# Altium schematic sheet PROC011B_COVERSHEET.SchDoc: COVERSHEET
size 431 x 279 mm; Date: Not shown in title block; ApprovedBy: Not shown in title block; CheckedBy: Not shown in title block; Author: Not shown in title block; CompanyName: Not shown in title block; Engineer: Not shown in title block; Organization: Not shown in title block; Address1: Not shown in title block; Address2: Not shown in title block; Address3: Not shown in title block; Address4: Not shown in title block; DocumentNumber: 1; Revision: Use project parameter SCH_Rev; SheetNumber: 1; SheetTotal: 17; PageSetup: Record=PageOptions¦CenterHorizontal=True¦CenterVertical=True¦PrintScale=0.64¦XCorrection=1.00¦YCorrection=1.00¦PrintKind=0¦BorderSize=5000000¦LeftOffset=0¦BottomOffset=0¦Orientation=2¦PaperLength=1000¦PaperWidth=1000¦Scale=100¦PaperSource=15¦PrintQuality=600¦MediaType=1¦DitherType=10¦PrintScaleMode=1¦PaperKind=Letter
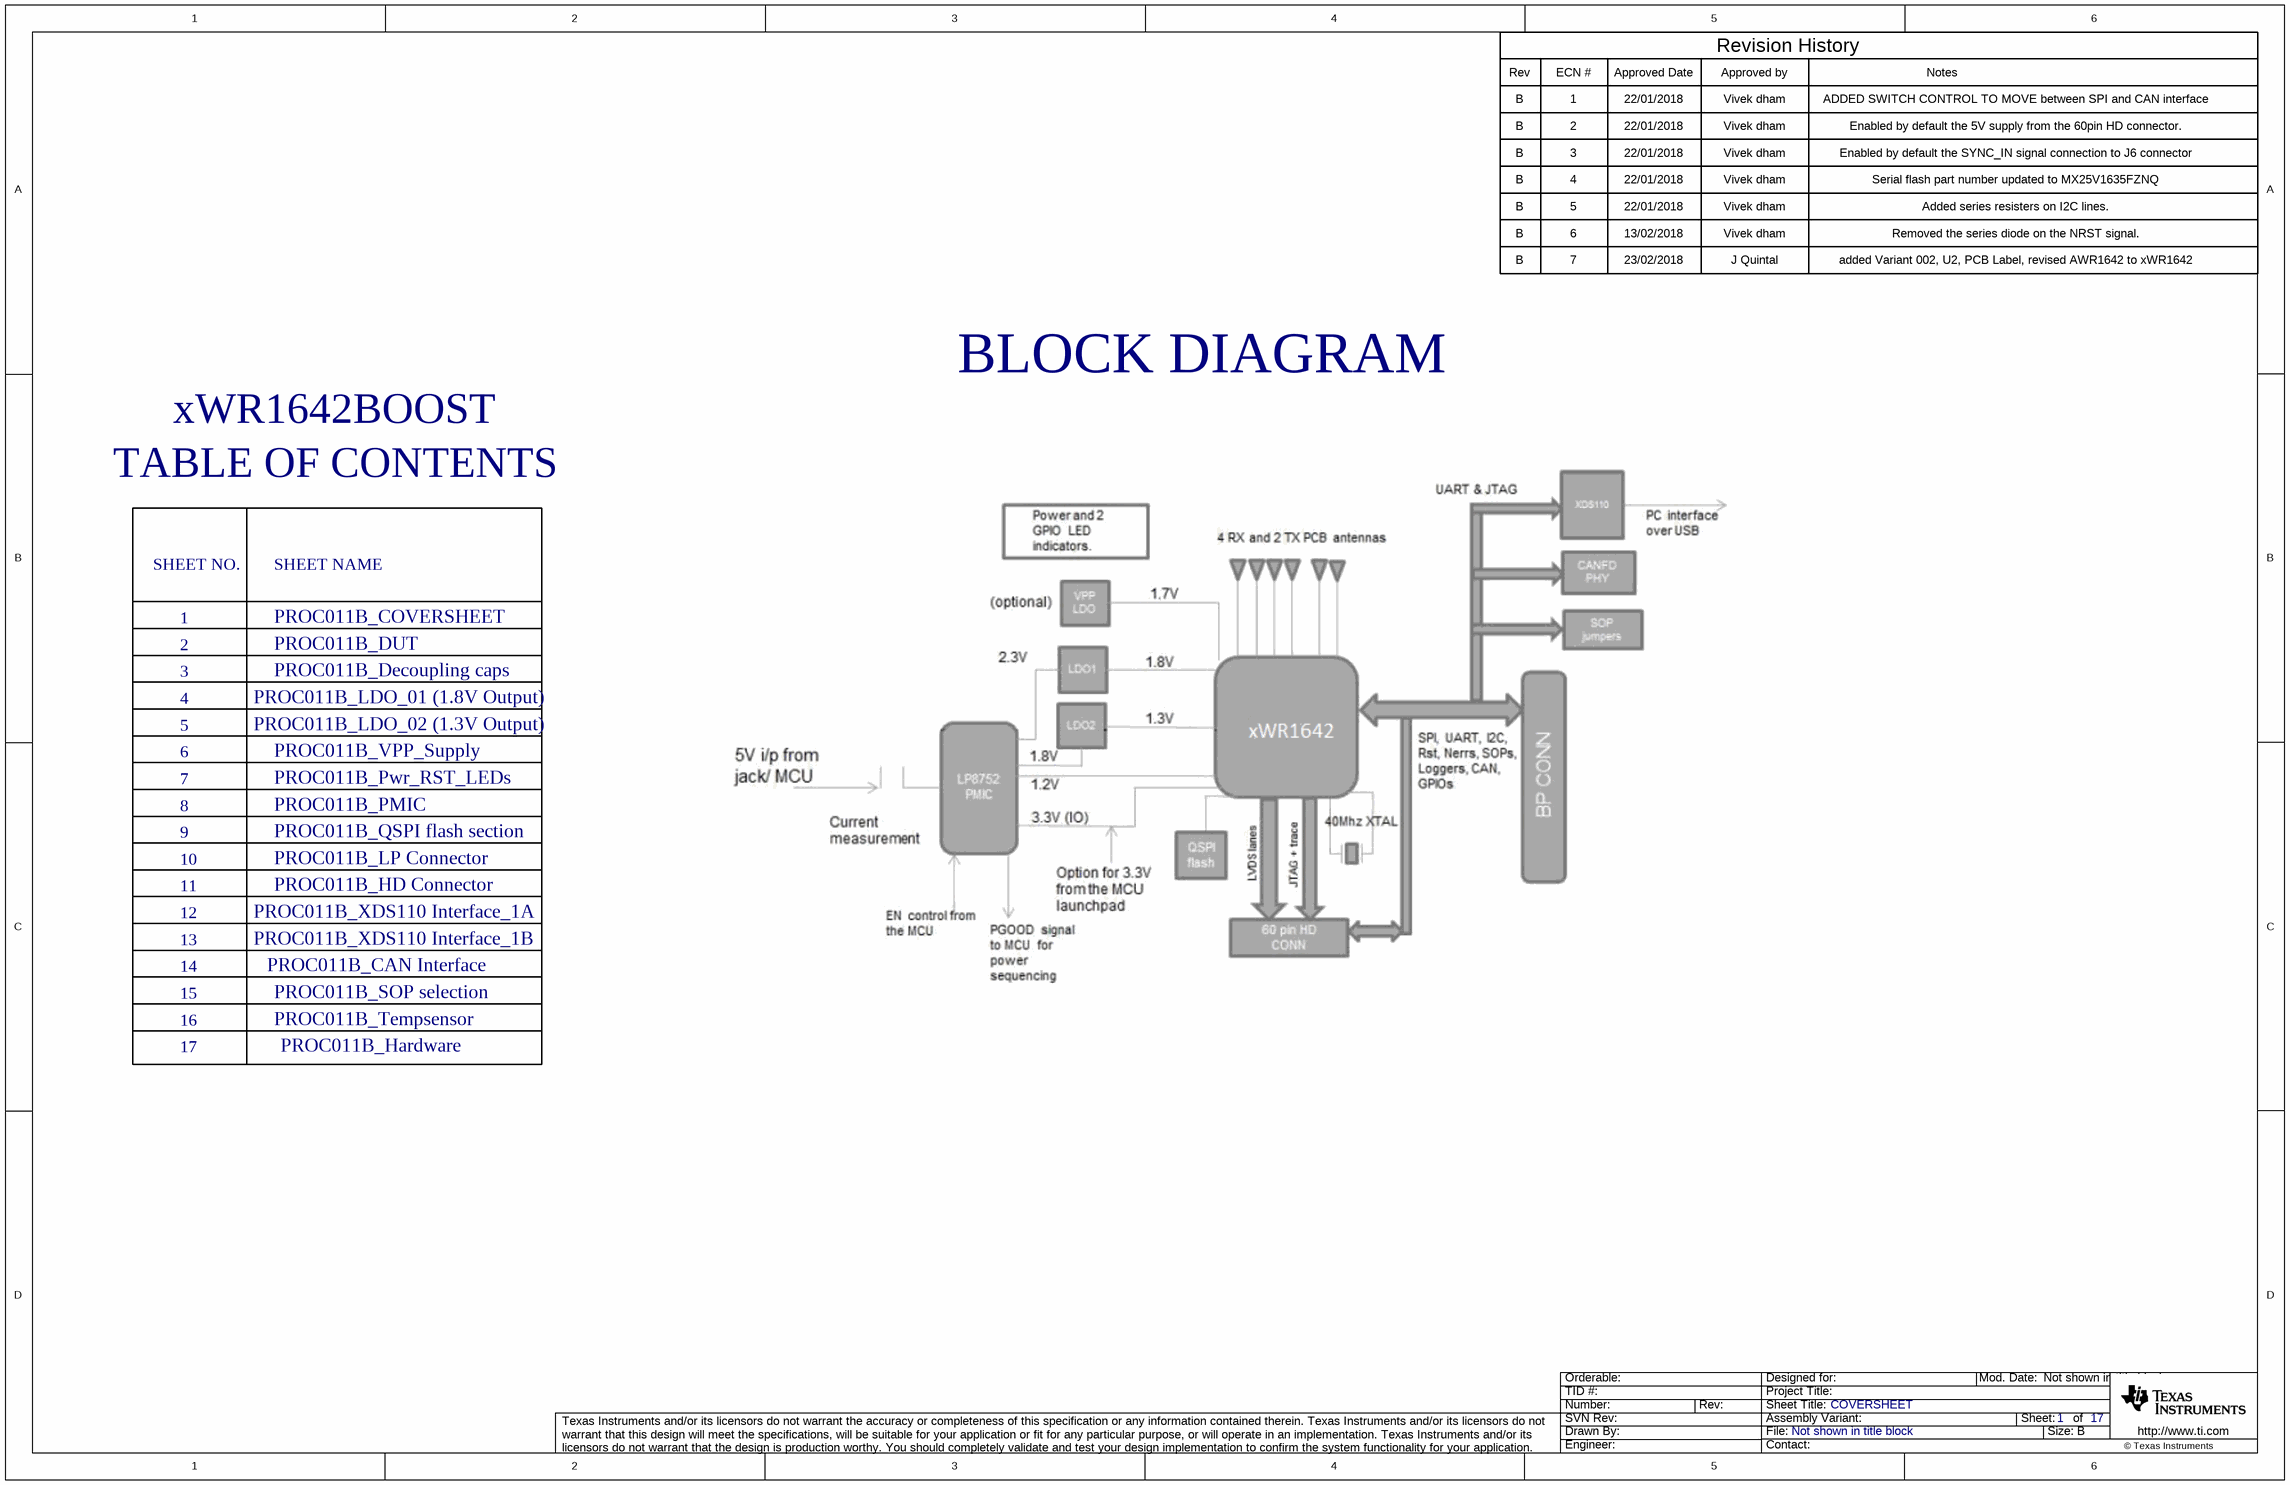
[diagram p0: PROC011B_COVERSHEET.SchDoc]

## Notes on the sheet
- Rev
- B
- ECN #
- 1
- Approved Date
- 22/01/2018
- Approved by
- Vivek dham
- Revision History
- Notes
- ADDED SWITCH CONTROL TO MOVE between SPI and CAN interface
- 2
- 3
- Enabled by default the 5V supply from the 60pin HD connector.
- Enabled by default the SYNC_IN signal connection to J6 connector
- 4
- 5
- 6
- 13/02/2018
- Serial flash part number updated to MX25V1635FZNQ
- Added series resisters on I2C lines.
- Removed the series diode on the NRST signal.
- 7
- 23/02/2018
- J Quintal
- added Variant 002, U2, PCB Label, revised AWR1642 to xWR1642
- xWR1642BOOST
- BLOCK DIAGRAM
- TABLE OF CONTENTS
- SHEET NO.
- SHEET NAME
- PROC011B_COVERSHEET
- PROC011B_LDO_01 (1.8V Output)
- PROC011B_DUT
- PROC011B_Decoupling caps
- PROC011B_LDO_02 (1.3V Output)
- PROC011B_VPP_Supply
- 8
- 9
- PROC011B_Pwr_RST_LEDs
- PROC011B_PMIC
- PROC011B_QSPI flash section
- 10
- 11
- PROC011B_LP Connector
- PROC011B_HD Connector
- 12
- 13
- 14
- PROC011B_XDS110 Interface_1A
- PROC011B_XDS110 Interface_1B
- PROC011B_CAN Interface
- 15
- 16
- PROC011B_SOP selection
- PROC011B_Tempsensor
- 17
- PROC011B_Hardware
